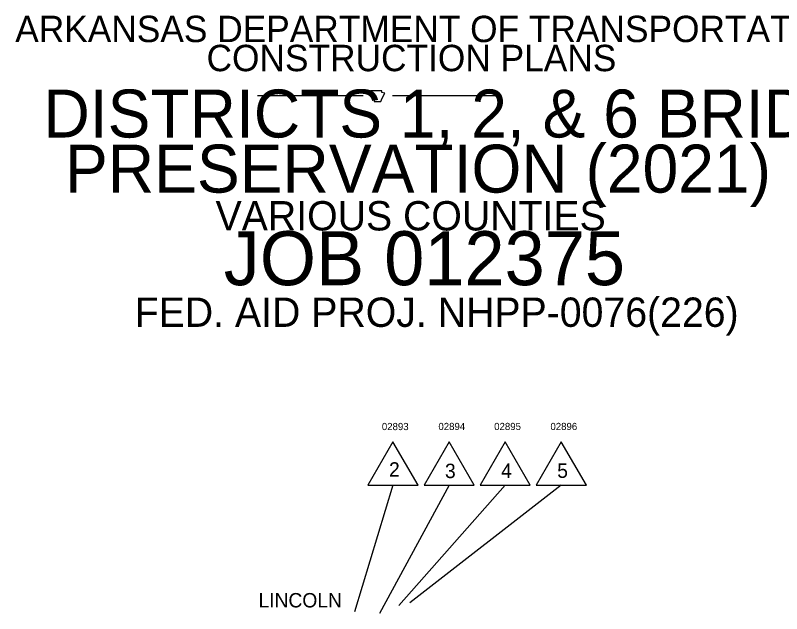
# Model space of a CAD drawing. Extents: x -31696 to 27919, y -8775 to 11152.
# Drawn here: x -4000 to 8778, y 1173 to 11152 of the extents above; entities that cross this region are included whole.
import ezdxf

# ---------------------------------------------------------------- set-up
doc = ezdxf.new("R2010")
doc.units = 0
for name, color, linetype in [('Level 1', 7, 'Continuous'), ('Level 2', 7, 'Continuous'), ('Level 48', 7, 'Continuous'), ('Level 50', 7, 'Continuous')]:
    doc.layers.add(name, color=color, linetype=linetype)

msp = doc.modelspace()

# ---------------------------------------------------------------- linework, layer by layer
at = {"layer": 'Level 1'}
for p, q in [((39, 9812), (1800, 9812)), ((2289, 9812), (4051, 9812))]:
    msp.add_line(p, q, dxfattribs=at)
msp.add_lwpolyline([(1915, 9901), (1952, 9803), (1952, 9743), (1982, 9736), (1982, 9714), (2094, 9714), (2116, 9773), (2161, 9856), (2108, 9862), (2108, 9893), (1923, 9893)], dxfattribs=at)
at = {"layer": 'Level 48'}
for p, q in [((2296, 4041), (1878, 3317)), ((2714, 3317), (2296, 4041)), ((3232, 4041), (2814, 3317)), ((3650, 3317), (3232, 4041)), ((4168, 4041), (3750, 3317)), ((4585, 3317), (4168, 4041)), ((5103, 4041), (4685, 3317)), ((5521, 3317), (5103, 4041)), ((2296, 3317), (1653, 1206)), ((1878, 3317), (2714, 3317)), ((3232, 3317), (2069, 1173)), ((4168, 3317), (2395, 1309)), ((5103, 3317), (2578, 1353)), ((2814, 3317), (3650, 3317)), ((3750, 3317), (4585, 3317)), ((4685, 3317), (5521, 3317))]:
    msp.add_line(p, q, dxfattribs=at)

# ---------------------------------------------------------------- texts
at = {"layer": 'Level 1'}
msp.add_text('FED. AID PROJ. NHPP-0076(226)', height=489.2, dxfattribs=at).set_placement((-2010, 5956))
at = {"layer": 'Level 2'}
for s, height, p in [('ARKANSAS DEPARTMENT OF TRANSPORTATION', 440, (-4002, 10705)), ('CONSTRUCTION PLANS', 440, (-812, 10220)), ('DISTRICTS 1, 2, & 6 BRIDGE', 800, (-3531, 9114)), ('PRESERVATION (2021) (S)', 800, (-3172, 8195)), ('VARIOUS COUNTIES', 489.2, (-662, 7564)), ('JOB 012375', 900, (-525, 6651)), ('LINCOLN', 240, (54, 1277))]:
    msp.add_text(s, height=height, dxfattribs=at).set_placement(p)
at = {"layer": 'Level 48'}
for s, p in [('2', (2231, 3458)), ('3', (3164, 3434)), ('4', (4100, 3438)), ('5', (5035, 3438))]:
    msp.add_text(s, height=240, dxfattribs=at).set_placement(p)
at = {"layer": 'Level 50'}
for s, p in [('02893', (2111, 4234)), ('02894', (3054, 4235)), ('02895', (3984, 4235)), ('02896', (4922, 4235))]:
    msp.add_text(s, height=120, dxfattribs=at).set_placement(p)

doc.saveas('drawing.dxf')
